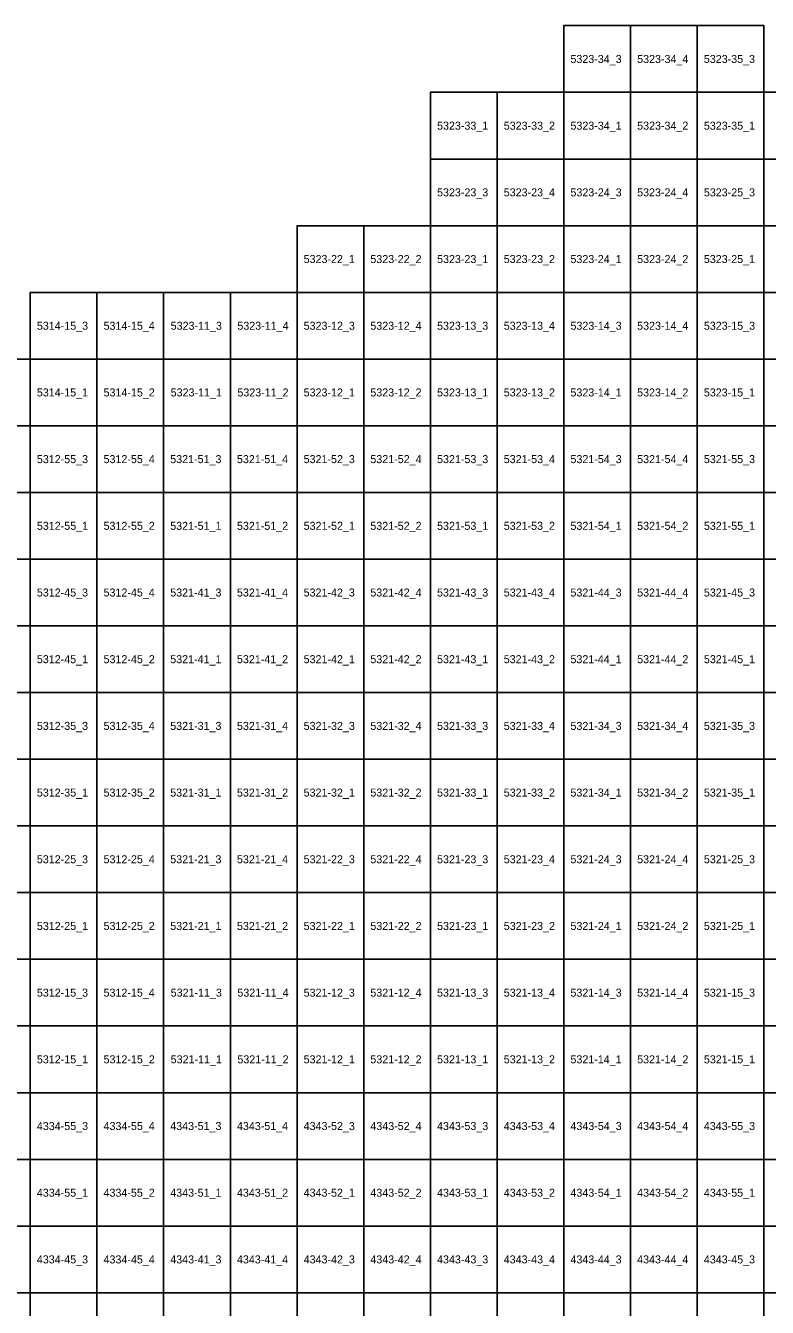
# Model space of a CAD drawing. Extents: x 312500 to 765000, y 172500 to 440000.
# Drawn here: x 544827 to 572629, y 391952 to 440000 of the extents above; entities that cross this region are included whole.
import ezdxf

# ---------------------------------------------------------------- set-up
doc = ezdxf.new("R2010")
doc.units = 0
doc.layers.add('Topo5_ramis_TKS2025', color=7, linetype='Continuous')
doc.layers.add('Topo5_ramis_TKS2025_Nr', color=7, linetype='Continuous')

msp = doc.modelspace()

# ---------------------------------------------------------------- linework, layer by layer
at = {"layer": 'Topo5_ramis_TKS2025'}
for points in [[(565000, 437500), (565000, 440000), (567500, 440000), (567500, 437500), (565000, 437500)], [(567500, 437500), (567500, 440000), (570000, 440000), (570000, 437500), (567500, 437500)], [(570000, 437500), (570000, 440000), (572500, 440000), (572500, 437500), (570000, 437500)], [(560000, 435000), (560000, 437500), (562500, 437500), (562500, 435000), (560000, 435000)], [(562500, 435000), (562500, 437500), (565000, 437500), (565000, 435000), (562500, 435000)], [(565000, 435000), (565000, 437500), (567500, 437500), (567500, 435000), (565000, 435000)], [(567500, 435000), (567500, 437500), (570000, 437500), (570000, 435000), (567500, 435000)], [(570000, 435000), (570000, 437500), (572500, 437500), (572500, 435000), (570000, 435000)], [(572500, 435000), (572500, 437500), (575000, 437500), (575000, 435000), (572500, 435000)], [(560000, 432500), (560000, 435000), (562500, 435000), (562500, 432500), (560000, 432500)], [(562500, 432500), (562500, 435000), (565000, 435000), (565000, 432500), (562500, 432500)], [(565000, 432500), (565000, 435000), (567500, 435000), (567500, 432500), (565000, 432500)], [(567500, 432500), (567500, 435000), (570000, 435000), (570000, 432500), (567500, 432500)], [(570000, 432500), (570000, 435000), (572500, 435000), (572500, 432500), (570000, 432500)], [(572500, 432500), (572500, 435000), (575000, 435000), (575000, 432500), (572500, 432500)], [(555000, 430000), (555000, 432500), (557500, 432500), (557500, 430000), (555000, 430000)], [(557500, 430000), (557500, 432500), (560000, 432500), (560000, 430000), (557500, 430000)], [(560000, 430000), (560000, 432500), (562500, 432500), (562500, 430000), (560000, 430000)], [(562500, 430000), (562500, 432500), (565000, 432500), (565000, 430000), (562500, 430000)], [(565000, 430000), (565000, 432500), (567500, 432500), (567500, 430000), (565000, 430000)], [(567500, 430000), (567500, 432500), (570000, 432500), (570000, 430000), (567500, 430000)], [(570000, 430000), (570000, 432500), (572500, 432500), (572500, 430000), (570000, 430000)], [(572500, 430000), (572500, 432500), (575000, 432500), (575000, 430000), (572500, 430000)], [(545000, 427500), (545000, 430000), (547500, 430000), (547500, 427500), (545000, 427500)], [(547500, 427500), (547500, 430000), (550000, 430000), (550000, 427500), (547500, 427500)], [(550000, 427500), (550000, 430000), (552500, 430000), (552500, 427500), (550000, 427500)], [(552500, 427500), (552500, 430000), (555000, 430000), (555000, 427500), (552500, 427500)], [(555000, 427500), (555000, 430000), (557500, 430000), (557500, 427500), (555000, 427500)], [(557500, 427500), (557500, 430000), (560000, 430000), (560000, 427500), (557500, 427500)], [(560000, 427500), (560000, 430000), (562500, 430000), (562500, 427500), (560000, 427500)], [(562500, 427500), (562500, 430000), (565000, 430000), (565000, 427500), (562500, 427500)], [(565000, 427500), (565000, 430000), (567500, 430000), (567500, 427500), (565000, 427500)], [(567500, 427500), (567500, 430000), (570000, 430000), (570000, 427500), (567500, 427500)], [(570000, 427500), (570000, 430000), (572500, 430000), (572500, 427500), (570000, 427500)], [(572500, 427500), (572500, 430000), (575000, 430000), (575000, 427500), (572500, 427500)], [(542500, 425000), (542500, 427500), (545000, 427500), (545000, 425000), (542500, 425000)], [(545000, 425000), (545000, 427500), (547500, 427500), (547500, 425000), (545000, 425000)], [(547500, 425000), (547500, 427500), (550000, 427500), (550000, 425000), (547500, 425000)], [(550000, 425000), (550000, 427500), (552500, 427500), (552500, 425000), (550000, 425000)], [(552500, 425000), (552500, 427500), (555000, 427500), (555000, 425000), (552500, 425000)], [(555000, 425000), (555000, 427500), (557500, 427500), (557500, 425000), (555000, 425000)], [(557500, 425000), (557500, 427500), (560000, 427500), (560000, 425000), (557500, 425000)], [(560000, 425000), (560000, 427500), (562500, 427500), (562500, 425000), (560000, 425000)], [(562500, 425000), (562500, 427500), (565000, 427500), (565000, 425000), (562500, 425000)], [(565000, 425000), (565000, 427500), (567500, 427500), (567500, 425000), (565000, 425000)], [(567500, 425000), (567500, 427500), (570000, 427500), (570000, 425000), (567500, 425000)], [(570000, 425000), (570000, 427500), (572500, 427500), (572500, 425000), (570000, 425000)], [(572500, 425000), (572500, 427500), (575000, 427500), (575000, 425000), (572500, 425000)], [(542500, 422500), (542500, 425000), (545000, 425000), (545000, 422500), (542500, 422500)], [(545000, 422500), (545000, 425000), (547500, 425000), (547500, 422500), (545000, 422500)], [(547500, 422500), (547500, 425000), (550000, 425000), (550000, 422500), (547500, 422500)], [(550000, 422500), (550000, 425000), (552500, 425000), (552500, 422500), (550000, 422500)], [(552500, 422500), (552500, 425000), (555000, 425000), (555000, 422500), (552500, 422500)], [(555000, 422500), (555000, 425000), (557500, 425000), (557500, 422500), (555000, 422500)], [(557500, 422500), (557500, 425000), (560000, 425000), (560000, 422500), (557500, 422500)], [(560000, 422500), (560000, 425000), (562500, 425000), (562500, 422500), (560000, 422500)], [(562500, 422500), (562500, 425000), (565000, 425000), (565000, 422500), (562500, 422500)], [(565000, 422500), (565000, 425000), (567500, 425000), (567500, 422500), (565000, 422500)], [(567500, 422500), (567500, 425000), (570000, 425000), (570000, 422500), (567500, 422500)], [(570000, 422500), (570000, 425000), (572500, 425000), (572500, 422500), (570000, 422500)], [(572500, 422500), (572500, 425000), (575000, 425000), (575000, 422500), (572500, 422500)], [(542500, 420000), (542500, 422500), (545000, 422500), (545000, 420000), (542500, 420000)], [(545000, 420000), (545000, 422500), (547500, 422500), (547500, 420000), (545000, 420000)], [(547500, 420000), (547500, 422500), (550000, 422500), (550000, 420000), (547500, 420000)], [(550000, 420000), (550000, 422500), (552500, 422500), (552500, 420000), (550000, 420000)], [(552500, 420000), (552500, 422500), (555000, 422500), (555000, 420000), (552500, 420000)], [(555000, 420000), (555000, 422500), (557500, 422500), (557500, 420000), (555000, 420000)], [(557500, 420000), (557500, 422500), (560000, 422500), (560000, 420000), (557500, 420000)], [(560000, 420000), (560000, 422500), (562500, 422500), (562500, 420000), (560000, 420000)], [(562500, 420000), (562500, 422500), (565000, 422500), (565000, 420000), (562500, 420000)], [(565000, 420000), (565000, 422500), (567500, 422500), (567500, 420000), (565000, 420000)], [(567500, 420000), (567500, 422500), (570000, 422500), (570000, 420000), (567500, 420000)], [(570000, 420000), (570000, 422500), (572500, 422500), (572500, 420000), (570000, 420000)], [(572500, 420000), (572500, 422500), (575000, 422500), (575000, 420000), (572500, 420000)], [(542500, 417500), (542500, 420000), (545000, 420000), (545000, 417500), (542500, 417500)], [(545000, 417500), (545000, 420000), (547500, 420000), (547500, 417500), (545000, 417500)], [(547500, 417500), (547500, 420000), (550000, 420000), (550000, 417500), (547500, 417500)], [(550000, 417500), (550000, 420000), (552500, 420000), (552500, 417500), (550000, 417500)], [(552500, 417500), (552500, 420000), (555000, 420000), (555000, 417500), (552500, 417500)], [(555000, 417500), (555000, 420000), (557500, 420000), (557500, 417500), (555000, 417500)], [(557500, 417500), (557500, 420000), (560000, 420000), (560000, 417500), (557500, 417500)], [(560000, 417500), (560000, 420000), (562500, 420000), (562500, 417500), (560000, 417500)], [(562500, 417500), (562500, 420000), (565000, 420000), (565000, 417500), (562500, 417500)], [(565000, 417500), (565000, 420000), (567500, 420000), (567500, 417500), (565000, 417500)], [(567500, 417500), (567500, 420000), (570000, 420000), (570000, 417500), (567500, 417500)], [(570000, 417500), (570000, 420000), (572500, 420000), (572500, 417500), (570000, 417500)], [(572500, 417500), (572500, 420000), (575000, 420000), (575000, 417500), (572500, 417500)], [(542500, 415000), (542500, 417500), (545000, 417500), (545000, 415000), (542500, 415000)], [(545000, 415000), (545000, 417500), (547500, 417500), (547500, 415000), (545000, 415000)], [(547500, 415000), (547500, 417500), (550000, 417500), (550000, 415000), (547500, 415000)], [(550000, 415000), (550000, 417500), (552500, 417500), (552500, 415000), (550000, 415000)], [(552500, 415000), (552500, 417500), (555000, 417500), (555000, 415000), (552500, 415000)], [(555000, 415000), (555000, 417500), (557500, 417500), (557500, 415000), (555000, 415000)], [(557500, 415000), (557500, 417500), (560000, 417500), (560000, 415000), (557500, 415000)], [(560000, 415000), (560000, 417500), (562500, 417500), (562500, 415000), (560000, 415000)], [(562500, 415000), (562500, 417500), (565000, 417500), (565000, 415000), (562500, 415000)], [(565000, 415000), (565000, 417500), (567500, 417500), (567500, 415000), (565000, 415000)], [(567500, 415000), (567500, 417500), (570000, 417500), (570000, 415000), (567500, 415000)], [(570000, 415000), (570000, 417500), (572500, 417500), (572500, 415000), (570000, 415000)], [(572500, 415000), (572500, 417500), (575000, 417500), (575000, 415000), (572500, 415000)], [(542500, 412500), (542500, 415000), (545000, 415000), (545000, 412500), (542500, 412500)], [(545000, 412500), (545000, 415000), (547500, 415000), (547500, 412500), (545000, 412500)], [(547500, 412500), (547500, 415000), (550000, 415000), (550000, 412500), (547500, 412500)], [(550000, 412500), (550000, 415000), (552500, 415000), (552500, 412500), (550000, 412500)], [(552500, 412500), (552500, 415000), (555000, 415000), (555000, 412500), (552500, 412500)], [(555000, 412500), (555000, 415000), (557500, 415000), (557500, 412500), (555000, 412500)], [(557500, 412500), (557500, 415000), (560000, 415000), (560000, 412500), (557500, 412500)], [(560000, 412500), (560000, 415000), (562500, 415000), (562500, 412500), (560000, 412500)], [(562500, 412500), (562500, 415000), (565000, 415000), (565000, 412500), (562500, 412500)], [(565000, 412500), (565000, 415000), (567500, 415000), (567500, 412500), (565000, 412500)], [(567500, 412500), (567500, 415000), (570000, 415000), (570000, 412500), (567500, 412500)], [(570000, 412500), (570000, 415000), (572500, 415000), (572500, 412500), (570000, 412500)], [(572500, 412500), (572500, 415000), (575000, 415000), (575000, 412500), (572500, 412500)], [(542500, 410000), (542500, 412500), (545000, 412500), (545000, 410000), (542500, 410000)], [(545000, 410000), (545000, 412500), (547500, 412500), (547500, 410000), (545000, 410000)], [(547500, 410000), (547500, 412500), (550000, 412500), (550000, 410000), (547500, 410000)], [(550000, 410000), (550000, 412500), (552500, 412500), (552500, 410000), (550000, 410000)], [(552500, 410000), (552500, 412500), (555000, 412500), (555000, 410000), (552500, 410000)], [(555000, 410000), (555000, 412500), (557500, 412500), (557500, 410000), (555000, 410000)], [(557500, 410000), (557500, 412500), (560000, 412500), (560000, 410000), (557500, 410000)], [(560000, 410000), (560000, 412500), (562500, 412500), (562500, 410000), (560000, 410000)], [(562500, 410000), (562500, 412500), (565000, 412500), (565000, 410000), (562500, 410000)], [(565000, 410000), (565000, 412500), (567500, 412500), (567500, 410000), (565000, 410000)], [(567500, 410000), (567500, 412500), (570000, 412500), (570000, 410000), (567500, 410000)], [(570000, 410000), (570000, 412500), (572500, 412500), (572500, 410000), (570000, 410000)], [(572500, 410000), (572500, 412500), (575000, 412500), (575000, 410000), (572500, 410000)], [(542500, 407500), (542500, 410000), (545000, 410000), (545000, 407500), (542500, 407500)], [(545000, 407500), (545000, 410000), (547500, 410000), (547500, 407500), (545000, 407500)], [(547500, 407500), (547500, 410000), (550000, 410000), (550000, 407500), (547500, 407500)], [(550000, 407500), (550000, 410000), (552500, 410000), (552500, 407500), (550000, 407500)], [(552500, 407500), (552500, 410000), (555000, 410000), (555000, 407500), (552500, 407500)], [(555000, 407500), (555000, 410000), (557500, 410000), (557500, 407500), (555000, 407500)], [(557500, 407500), (557500, 410000), (560000, 410000), (560000, 407500), (557500, 407500)], [(560000, 407500), (560000, 410000), (562500, 410000), (562500, 407500), (560000, 407500)], [(562500, 407500), (562500, 410000), (565000, 410000), (565000, 407500), (562500, 407500)], [(565000, 407500), (565000, 410000), (567500, 410000), (567500, 407500), (565000, 407500)], [(567500, 407500), (567500, 410000), (570000, 410000), (570000, 407500), (567500, 407500)], [(570000, 407500), (570000, 410000), (572500, 410000), (572500, 407500), (570000, 407500)], [(572500, 407500), (572500, 410000), (575000, 410000), (575000, 407500), (572500, 407500)], [(542500, 405000), (542500, 407500), (545000, 407500), (545000, 405000), (542500, 405000)], [(545000, 405000), (545000, 407500), (547500, 407500), (547500, 405000), (545000, 405000)], [(547500, 405000), (547500, 407500), (550000, 407500), (550000, 405000), (547500, 405000)], [(550000, 405000), (550000, 407500), (552500, 407500), (552500, 405000), (550000, 405000)], [(552500, 405000), (552500, 407500), (555000, 407500), (555000, 405000), (552500, 405000)], [(555000, 405000), (555000, 407500), (557500, 407500), (557500, 405000), (555000, 405000)], [(557500, 405000), (557500, 407500), (560000, 407500), (560000, 405000), (557500, 405000)], [(560000, 405000), (560000, 407500), (562500, 407500), (562500, 405000), (560000, 405000)], [(562500, 405000), (562500, 407500), (565000, 407500), (565000, 405000), (562500, 405000)], [(565000, 405000), (565000, 407500), (567500, 407500), (567500, 405000), (565000, 405000)], [(567500, 405000), (567500, 407500), (570000, 407500), (570000, 405000), (567500, 405000)], [(570000, 405000), (570000, 407500), (572500, 407500), (572500, 405000), (570000, 405000)], [(572500, 405000), (572500, 407500), (575000, 407500), (575000, 405000), (572500, 405000)], [(542500, 402500), (542500, 405000), (545000, 405000), (545000, 402500), (542500, 402500)], [(545000, 402500), (545000, 405000), (547500, 405000), (547500, 402500), (545000, 402500)], [(547500, 402500), (547500, 405000), (550000, 405000), (550000, 402500), (547500, 402500)], [(550000, 402500), (550000, 405000), (552500, 405000), (552500, 402500), (550000, 402500)], [(552500, 402500), (552500, 405000), (555000, 405000), (555000, 402500), (552500, 402500)], [(555000, 402500), (555000, 405000), (557500, 405000), (557500, 402500), (555000, 402500)], [(557500, 402500), (557500, 405000), (560000, 405000), (560000, 402500), (557500, 402500)], [(560000, 402500), (560000, 405000), (562500, 405000), (562500, 402500), (560000, 402500)], [(562500, 402500), (562500, 405000), (565000, 405000), (565000, 402500), (562500, 402500)], [(565000, 402500), (565000, 405000), (567500, 405000), (567500, 402500), (565000, 402500)], [(567500, 402500), (567500, 405000), (570000, 405000), (570000, 402500), (567500, 402500)], [(570000, 402500), (570000, 405000), (572500, 405000), (572500, 402500), (570000, 402500)], [(572500, 402500), (572500, 405000), (575000, 405000), (575000, 402500), (572500, 402500)], [(542500, 400000), (542500, 402500), (545000, 402500), (545000, 400000), (542500, 400000)], [(545000, 400000), (545000, 402500), (547500, 402500), (547500, 400000), (545000, 400000)], [(547500, 400000), (547500, 402500), (550000, 402500), (550000, 400000), (547500, 400000)], [(550000, 400000), (550000, 402500), (552500, 402500), (552500, 400000), (550000, 400000)], [(552500, 400000), (552500, 402500), (555000, 402500), (555000, 400000), (552500, 400000)], [(555000, 400000), (555000, 402500), (557500, 402500), (557500, 400000), (555000, 400000)], [(557500, 400000), (557500, 402500), (560000, 402500), (560000, 400000), (557500, 400000)], [(560000, 400000), (560000, 402500), (562500, 402500), (562500, 400000), (560000, 400000)], [(562500, 400000), (562500, 402500), (565000, 402500), (565000, 400000), (562500, 400000)], [(565000, 400000), (565000, 402500), (567500, 402500), (567500, 400000), (565000, 400000)], [(567500, 400000), (567500, 402500), (570000, 402500), (570000, 400000), (567500, 400000)], [(570000, 400000), (570000, 402500), (572500, 402500), (572500, 400000), (570000, 400000)], [(572500, 400000), (572500, 402500), (575000, 402500), (575000, 400000), (572500, 400000)], [(542500, 397500), (542500, 400000), (545000, 400000), (545000, 397500), (542500, 397500)], [(545000, 397500), (545000, 400000), (547500, 400000), (547500, 397500), (545000, 397500)], [(547500, 397500), (547500, 400000), (550000, 400000), (550000, 397500), (547500, 397500)], [(550000, 397500), (550000, 400000), (552500, 400000), (552500, 397500), (550000, 397500)], [(552500, 397500), (552500, 400000), (555000, 400000), (555000, 397500), (552500, 397500)], [(555000, 397500), (555000, 400000), (557500, 400000), (557500, 397500), (555000, 397500)], [(557500, 397500), (557500, 400000), (560000, 400000), (560000, 397500), (557500, 397500)], [(560000, 397500), (560000, 400000), (562500, 400000), (562500, 397500), (560000, 397500)], [(562500, 397500), (562500, 400000), (565000, 400000), (565000, 397500), (562500, 397500)], [(565000, 397500), (565000, 400000), (567500, 400000), (567500, 397500), (565000, 397500)], [(567500, 397500), (567500, 400000), (570000, 400000), (570000, 397500), (567500, 397500)], [(570000, 397500), (570000, 400000), (572500, 400000), (572500, 397500), (570000, 397500)], [(572500, 397500), (572500, 400000), (575000, 400000), (575000, 397500), (572500, 397500)], [(542500, 395000), (542500, 397500), (545000, 397500), (545000, 395000), (542500, 395000)], [(545000, 395000), (545000, 397500), (547500, 397500), (547500, 395000), (545000, 395000)], [(547500, 395000), (547500, 397500), (550000, 397500), (550000, 395000), (547500, 395000)], [(550000, 395000), (550000, 397500), (552500, 397500), (552500, 395000), (550000, 395000)], [(552500, 395000), (552500, 397500), (555000, 397500), (555000, 395000), (552500, 395000)], [(555000, 395000), (555000, 397500), (557500, 397500), (557500, 395000), (555000, 395000)], [(557500, 395000), (557500, 397500), (560000, 397500), (560000, 395000), (557500, 395000)], [(560000, 395000), (560000, 397500), (562500, 397500), (562500, 395000), (560000, 395000)], [(562500, 395000), (562500, 397500), (565000, 397500), (565000, 395000), (562500, 395000)], [(565000, 395000), (565000, 397500), (567500, 397500), (567500, 395000), (565000, 395000)], [(567500, 395000), (567500, 397500), (570000, 397500), (570000, 395000), (567500, 395000)], [(570000, 395000), (570000, 397500), (572500, 397500), (572500, 395000), (570000, 395000)], [(572500, 395000), (572500, 397500), (575000, 397500), (575000, 395000), (572500, 395000)], [(542500, 392500), (542500, 395000), (545000, 395000), (545000, 392500), (542500, 392500)], [(545000, 392500), (545000, 395000), (547500, 395000), (547500, 392500), (545000, 392500)], [(547500, 392500), (547500, 395000), (550000, 395000), (550000, 392500), (547500, 392500)], [(550000, 392500), (550000, 395000), (552500, 395000), (552500, 392500), (550000, 392500)], [(552500, 392500), (552500, 395000), (555000, 395000), (555000, 392500), (552500, 392500)], [(555000, 392500), (555000, 395000), (557500, 395000), (557500, 392500), (555000, 392500)], [(557500, 392500), (557500, 395000), (560000, 395000), (560000, 392500), (557500, 392500)], [(560000, 392500), (560000, 395000), (562500, 395000), (562500, 392500), (560000, 392500)], [(562500, 392500), (562500, 395000), (565000, 395000), (565000, 392500), (562500, 392500)], [(565000, 392500), (565000, 395000), (567500, 395000), (567500, 392500), (565000, 392500)], [(567500, 392500), (567500, 395000), (570000, 395000), (570000, 392500), (567500, 392500)], [(570000, 392500), (570000, 395000), (572500, 395000), (572500, 392500), (570000, 392500)], [(572500, 392500), (572500, 395000), (575000, 395000), (575000, 392500), (572500, 392500)], [(542500, 390000), (542500, 392500), (545000, 392500), (545000, 390000), (542500, 390000)], [(545000, 390000), (545000, 392500), (547500, 392500), (547500, 390000), (545000, 390000)], [(547500, 390000), (547500, 392500), (550000, 392500), (550000, 390000), (547500, 390000)], [(550000, 390000), (550000, 392500), (552500, 392500), (552500, 390000), (550000, 390000)], [(552500, 390000), (552500, 392500), (555000, 392500), (555000, 390000), (552500, 390000)], [(555000, 390000), (555000, 392500), (557500, 392500), (557500, 390000), (555000, 390000)], [(557500, 390000), (557500, 392500), (560000, 392500), (560000, 390000), (557500, 390000)], [(560000, 390000), (560000, 392500), (562500, 392500), (562500, 390000), (560000, 390000)], [(562500, 390000), (562500, 392500), (565000, 392500), (565000, 390000), (562500, 390000)], [(565000, 390000), (565000, 392500), (567500, 392500), (567500, 390000), (565000, 390000)], [(567500, 390000), (567500, 392500), (570000, 392500), (570000, 390000), (567500, 390000)], [(570000, 390000), (570000, 392500), (572500, 392500), (572500, 390000), (570000, 390000)], [(572500, 390000), (572500, 392500), (575000, 392500), (575000, 390000), (572500, 390000)]]:
    msp.add_lwpolyline(points, dxfattribs=at)

# ---------------------------------------------------------------- texts
at = {"layer": 'Topo5_ramis_TKS2025_Nr'}
for s, p in [('5323-34_3', (565248, 438600)), ('5323-34_4', (567748, 438600)), ('5323-35_3', (570248, 438600)), ('5323-33_1', (560248, 436100)), ('5323-33_2', (562748, 436100)), ('5323-34_1', (565248, 436100)), ('5323-34_2', (567748, 436100)), ('5323-35_1', (570248, 436100)), ('5323-23_3', (560248, 433600)), ('5323-23_4', (562748, 433600)), ('5323-24_3', (565248, 433600)), ('5323-24_4', (567748, 433600)), ('5323-25_3', (570248, 433600)), ('5323-22_1', (555248, 431100)), ('5323-22_2', (557748, 431100)), ('5323-23_1', (560248, 431100)), ('5323-23_2', (562748, 431100)), ('5323-24_1', (565248, 431100)), ('5323-24_2', (567748, 431100)), ('5323-25_1', (570248, 431100)), ('5314-15_3', (545248, 428600)), ('5314-15_4', (547748, 428600)), ('5323-11_3', (550264, 428600)), ('5323-11_4', (552764, 428600)), ('5323-12_3', (555248, 428600)), ('5323-12_4', (557748, 428600)), ('5323-13_3', (560248, 428600)), ('5323-13_4', (562748, 428600)), ('5323-14_3', (565248, 428600)), ('5323-14_4', (567748, 428600)), ('5323-15_3', (570248, 428600)), ('5314-15_1', (545248, 426100)), ('5314-15_2', (547748, 426100)), ('5323-11_1', (550264, 426100)), ('5323-11_2', (552764, 426100)), ('5323-12_1', (555248, 426100)), ('5323-12_2', (557748, 426100)), ('5323-13_1', (560248, 426100)), ('5323-13_2', (562748, 426100)), ('5323-14_1', (565248, 426100)), ('5323-14_2', (567748, 426100)), ('5323-15_1', (570248, 426100)), ('5312-55_3', (545248, 423600)), ('5312-55_4', (547748, 423600)), ('5321-51_3', (550248, 423600)), ('5321-51_4', (552748, 423600)), ('5321-52_3', (555248, 423600)), ('5321-52_4', (557748, 423600)), ('5321-53_3', (560248, 423600)), ('5321-53_4', (562748, 423600)), ('5321-54_3', (565248, 423600)), ('5321-54_4', (567748, 423600)), ('5321-55_3', (570248, 423600)), ('5312-55_1', (545248, 421100)), ('5312-55_2', (547748, 421100)), ('5321-51_1', (550248, 421100)), ('5321-51_2', (552748, 421100)), ('5321-52_1', (555248, 421100)), ('5321-52_2', (557748, 421100)), ('5321-53_1', (560248, 421100)), ('5321-53_2', (562748, 421100)), ('5321-54_1', (565248, 421100)), ('5321-54_2', (567748, 421100)), ('5321-55_1', (570248, 421100)), ('5312-45_3', (545248, 418600)), ('5312-45_4', (547748, 418600)), ('5321-41_3', (550248, 418600)), ('5321-41_4', (552748, 418600)), ('5321-42_3', (555248, 418600)), ('5321-42_4', (557748, 418600)), ('5321-43_3', (560248, 418600)), ('5321-43_4', (562748, 418600)), ('5321-44_3', (565248, 418600)), ('5321-44_4', (567748, 418600)), ('5321-45_3', (570248, 418600)), ('5312-45_1', (545248, 416100)), ('5312-45_2', (547748, 416100)), ('5321-41_1', (550248, 416100)), ('5321-41_2', (552748, 416100)), ('5321-42_1', (555248, 416100)), ('5321-42_2', (557748, 416100)), ('5321-43_1', (560248, 416100)), ('5321-43_2', (562748, 416100)), ('5321-44_1', (565248, 416100)), ('5321-44_2', (567748, 416100)), ('5321-45_1', (570248, 416100)), ('5312-35_3', (545248, 413600)), ('5312-35_4', (547748, 413600)), ('5321-31_3', (550248, 413600)), ('5321-31_4', (552748, 413600)), ('5321-32_3', (555248, 413600)), ('5321-32_4', (557748, 413600)), ('5321-33_3', (560248, 413600)), ('5321-33_4', (562748, 413600)), ('5321-34_3', (565248, 413600)), ('5321-34_4', (567748, 413600)), ('5321-35_3', (570248, 413600)), ('5312-35_1', (545248, 411100)), ('5312-35_2', (547748, 411100)), ('5321-31_1', (550248, 411100)), ('5321-31_2', (552748, 411100)), ('5321-32_1', (555248, 411100)), ('5321-32_2', (557748, 411100)), ('5321-33_1', (560248, 411100)), ('5321-33_2', (562748, 411100)), ('5321-34_1', (565248, 411100)), ('5321-34_2', (567748, 411100)), ('5321-35_1', (570248, 411100)), ('5312-25_3', (545248, 408600)), ('5312-25_4', (547748, 408600)), ('5321-21_3', (550248, 408600)), ('5321-21_4', (552748, 408600)), ('5321-22_3', (555248, 408600)), ('5321-22_4', (557748, 408600)), ('5321-23_3', (560248, 408600)), ('5321-23_4', (562748, 408600)), ('5321-24_3', (565248, 408600)), ('5321-24_4', (567748, 408600)), ('5321-25_3', (570248, 408600)), ('5312-25_1', (545248, 406100)), ('5312-25_2', (547748, 406100)), ('5321-21_1', (550248, 406100)), ('5321-21_2', (552748, 406100)), ('5321-22_1', (555248, 406100)), ('5321-22_2', (557748, 406100)), ('5321-23_1', (560248, 406100)), ('5321-23_2', (562748, 406100)), ('5321-24_1', (565248, 406100)), ('5321-24_2', (567748, 406100)), ('5321-25_1', (570248, 406100)), ('5312-15_3', (545248, 403600)), ('5312-15_4', (547748, 403600)), ('5321-11_3', (550264, 403600)), ('5321-11_4', (552764, 403600)), ('5321-12_3', (555248, 403600)), ('5321-12_4', (557748, 403600)), ('5321-13_3', (560248, 403600)), ('5321-13_4', (562748, 403600)), ('5321-14_3', (565248, 403600)), ('5321-14_4', (567748, 403600)), ('5321-15_3', (570248, 403600)), ('5312-15_1', (545248, 401100)), ('5312-15_2', (547748, 401100)), ('5321-11_1', (550264, 401100)), ('5321-11_2', (552764, 401100)), ('5321-12_1', (555248, 401100)), ('5321-12_2', (557748, 401100)), ('5321-13_1', (560248, 401100)), ('5321-13_2', (562748, 401100)), ('5321-14_1', (565248, 401100)), ('5321-14_2', (567748, 401100)), ('5321-15_1', (570248, 401100)), ('4334-55_3', (545248, 398600)), ('4334-55_4', (547748, 398600)), ('4343-51_3', (550248, 398600)), ('4343-51_4', (552748, 398600)), ('4343-52_3', (555248, 398600)), ('4343-52_4', (557748, 398600)), ('4343-53_3', (560248, 398600)), ('4343-53_4', (562748, 398600)), ('4343-54_3', (565248, 398600)), ('4343-54_4', (567748, 398600)), ('4343-55_3', (570248, 398600)), ('4334-55_1', (545248, 396100)), ('4334-55_2', (547748, 396100)), ('4343-51_1', (550248, 396100)), ('4343-51_2', (552748, 396100)), ('4343-52_1', (555248, 396100)), ('4343-52_2', (557748, 396100)), ('4343-53_1', (560248, 396100)), ('4343-53_2', (562748, 396100)), ('4343-54_1', (565248, 396100)), ('4343-54_2', (567748, 396100)), ('4343-55_1', (570248, 396100)), ('4334-45_3', (545248, 393600)), ('4334-45_4', (547748, 393600)), ('4343-41_3', (550248, 393600)), ('4343-41_4', (552748, 393600)), ('4343-42_3', (555248, 393600)), ('4343-42_4', (557748, 393600)), ('4343-43_3', (560248, 393600)), ('4343-43_4', (562748, 393600)), ('4343-44_3', (565248, 393600)), ('4343-44_4', (567748, 393600)), ('4343-45_3', (570248, 393600))]:
    msp.add_text(s, height=300, dxfattribs=at).set_placement(p)

doc.saveas('drawing.dxf')
